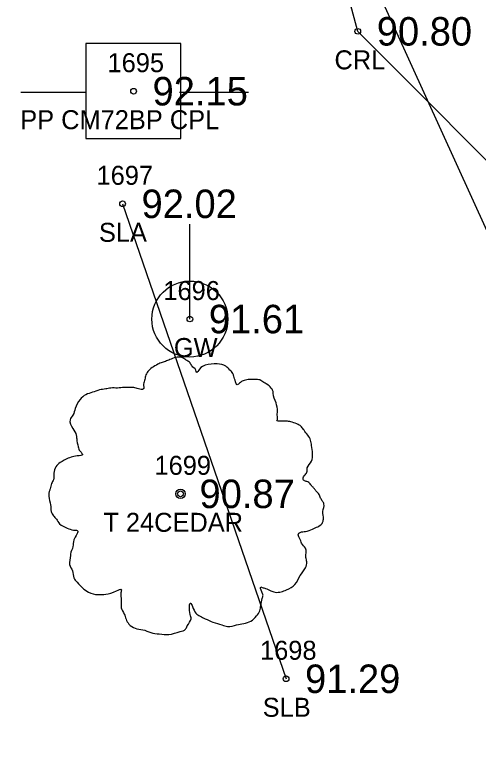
# Model space of a CAD drawing. Extents: x 2529517 to 2532038, y 935000 to 936944.
# Drawn here: x 2531034.45 to 2531058.87, y 935944.18 to 935982.7 of the extents above; entities that cross this region are included whole.
import ezdxf

# ---------------------------------------------------------------- set-up
doc = ezdxf.new("R2010")
doc.units = 0
for name, color, linetype in [('RD_EX_H2O', 7, 'Continuous'), ('RD_EX_H2O_txCode', 7, 'Continuous'), ('RD_EX_TX_H2O_ELEV', 7, 'Continuous'), ('RD_EX_TX_UT_ELEV', 7, 'Continuous'), ('RD_EX_TX_VEG_ELEV', 7, 'Continuous'), ('RD_EX_UT', 7, 'Continuous'), ('RD_EX_UT_txCode', 7, 'Continuous'), ('RD_EX_VEG', 7, 'Continuous'), ('RD_EX_VEG_txCode', 7, 'Continuous'), ('RD_HC_Survey_ELEV', 7, 'Continuous'), ('RD_SMD_Locator', 7, 'Continuous')]:
    doc.layers.add(name, color=color, linetype=linetype)

msp = doc.modelspace()

# ---------------------------------------------------------------- linework, layer by layer
at = {"layer": 'RD_EX_H2O'}
msp.add_lwpolyline([(2531078.875, 935952.281), (2531078.875, 935952.281), (2531082.899, 935955.367), (2531071.893, 935962.427), (2531052.521, 935981.817), (2531042.661, 936018.537), (2531050.401, 936038.586), (2531079.351, 936050.478), (2531076.459, 936052.289), (2531062.769, 936059.407), (2531060.273, 936060.115), (2531061.981, 936077.759), (2531053.988, 936081.477), (2531023.23, 936060.573), (2531009.04, 936063.638), (2530981.915, 936072.848), (2530952.276, 936069.689), (2530922.526, 936086.42), (2530896.36, 936118.007), (2530886.535, 936120.086), (2530870.436, 936126.503), (2530844.881, 936119.109), (2530827.398, 936131.929), (2530794.882, 936161.74)], dxfattribs=at)
at = {"layer": 'RD_EX_UT'}
for p, q in [((2531043.202, 935981.176), (2531038.202, 935981.176)), ((2531038.202, 935981.176), (2531038.202, 935976.176)), ((2531043.202, 935976.176), (2531043.202, 935981.176)), ((2531034.771, 935978.613), (2531038.241, 935978.613)), ((2531043.131, 935978.613), (2531046.771, 935978.613)), ((2531038.202, 935976.176), (2531043.202, 935976.176)), ((2531043.676, 935966.674), (2531043.676, 935971.674))]:
    msp.add_line(p, q, dxfattribs=at)
msp.add_circle((2531043.676, 935966.674), 1.999, dxfattribs=at)
at = {"layer": 'RD_EX_VEG'}
msp.add_line((2531040.132, 935972.739), (2531048.743, 935947.739), dxfattribs=at)
msp.add_lwpolyline([(2531065.966, 935956.737), (2531029.723, 936036.27), (2530913.111, 935955.889), (2530857.851, 935929.004), (2530845.595, 935970.773)], dxfattribs=at)
for centre, radius in [((2531043.184, 935957.474), 0.25), ((2531043.171, 935957.455), 0.0001)]:
    msp.add_circle(centre, radius, dxfattribs=at)
for points in [[(2531043.316, 935964.641), (2531043.016, 935964.666), (2531042.691, 935964.566), (2531042.441, 935964.466), (2531042.216, 935964.391), (2531041.991, 935964.291), (2531041.691, 935964.116), (2531041.467, 935963.916), (2531041.342, 935963.666), (2531041.292, 935963.442), (2531041.242, 935963.167), (2531041.242, 935962.992), (2531041.117, 935962.967), (2531040.967, 935962.992), (2531040.717, 935963.067), (2531040.467, 935963.067), (2531040.217, 935963.067), (2531039.867, 935963.042), (2531039.517, 935963.042), (2531039.243, 935962.992), (2531038.918, 935962.942), (2531038.543, 935962.817), (2531038.193, 935962.692), (2531037.893, 935962.442), (2531037.643, 935961.967), (2531037.518, 935961.617), (2531037.368, 935961.367), (2531037.518, 935960.918), (2531037.693, 935960.568), (2531037.718, 935960.368), (2531037.793, 935959.943), (2531037.893, 935959.718), (2531038.018, 935959.518), (2531037.943, 935959.493), (2531037.568, 935959.443), (2531037.268, 935959.343), (2531036.844, 935959.118), (2531036.619, 935958.894), (2531036.519, 935958.569), (2531036.494, 935958.219), (2531036.394, 935958.019), (2531036.319, 935957.744), (2531036.294, 935957.669), (2531036.244, 935957.344), (2531036.344, 935956.894), (2531036.369, 935956.545), (2531036.494, 935956.32), (2531036.644, 935956.145), (2531036.819, 935955.895), (2531037.218, 935955.67), (2531037.543, 935955.57), (2531037.743, 935955.545), (2531037.568, 935955.045), (2531037.518, 935954.695), (2531037.393, 935954.296), (2531037.393, 935954.221), (2531037.343, 935953.746), (2531037.493, 935953.421), (2531037.568, 935953.046), (2531037.743, 935952.821), (2531038.018, 935952.521), (2531038.343, 935952.296), (2531038.843, 935952.171), (2531039.243, 935952.196), (2531039.817, 935952.371), (2531040.067, 935952.446), (2531040.042, 935952.271), (2531040.067, 935951.897), (2531040.067, 935951.472), (2531040.217, 935951.147), (2531040.317, 935950.872), (2531040.467, 935950.622), (2531040.792, 935950.397), (2531041.192, 935950.322), (2531041.616, 935950.172), (2531042.066, 935950.097), (2531042.566, 935950.072), (2531043.166, 935950.222), (2531043.441, 935950.347), (2531043.541, 935950.522), (2531043.741, 935950.897), (2531043.691, 935951.122), (2531043.716, 935951.722), (2531043.815, 935951.547), (2531043.99, 935951.197), (2531044.49, 935950.897), (2531044.89, 935950.722), (2531045.365, 935950.572), (2531045.665, 935950.497), (2531046.139, 935950.572), (2531046.514, 935950.647), (2531046.889, 935950.772), (2531047.189, 935951.047), (2531047.364, 935951.322), (2531047.414, 935951.597), (2531047.489, 935951.972), (2531047.539, 935952.146)], [(2531047.539, 935952.146), (2531047.464, 935952.321), (2531047.414, 935952.571), (2531047.489, 935952.546), (2531047.664, 935952.496), (2531047.939, 935952.371), (2531048.164, 935952.296), (2531048.488, 935952.321), (2531048.763, 935952.421), (2531049.213, 935952.696), (2531049.488, 935953.171), (2531049.763, 935953.571), (2531049.838, 935953.896), (2531049.788, 935954.121), (2531049.763, 935954.62), (2531049.563, 935954.87), (2531049.513, 935954.995), (2531049.413, 935955.395), (2531049.488, 935955.445), (2531049.763, 935955.495), (2531050.138, 935955.62), (2531050.413, 935955.745), (2531050.638, 935955.92), (2531050.712, 935956.145), (2531050.688, 935956.545), (2531050.737, 935956.944), (2531050.663, 935957.094), (2531050.563, 935957.244), (2531050.488, 935957.444), (2531050.338, 935957.594), (2531050.238, 935957.744), (2531050.138, 935957.844), (2531050.013, 935957.994), (2531049.838, 935958.119), (2531049.688, 935958.169), (2531049.638, 935958.319), (2531049.788, 935958.519), (2531049.838, 935958.619), (2531049.863, 935958.844), (2531050.088, 935959.193), (2531050.138, 935959.593), (2531050.088, 935960.018), (2531050.038, 935960.293), (2531049.888, 935960.568), (2531049.688, 935960.818), (2531049.563, 935960.993), (2531049.388, 935961.118), (2531049.063, 935961.243), (2531048.813, 935961.292), (2531048.463, 935961.292), (2531048.264, 935961.342), (2531048.289, 935961.392), (2531048.289, 935961.542), (2531048.289, 935961.817), (2531048.214, 935962.267), (2531048.064, 935962.767), (2531048.064, 935962.792), (2531047.964, 935963.042), (2531047.739, 935963.242), (2531047.564, 935963.342), (2531047.364, 935963.467), (2531047.114, 935963.492), (2531046.814, 935963.492), (2531046.539, 935963.442), (2531046.339, 935963.342), (2531046.164, 935963.217), (2531046.089, 935963.367), (2531045.99, 935963.666), (2531045.94, 935963.816), (2531045.79, 935963.991), (2531045.565, 935964.191), (2531045.115, 935964.316), (2531044.49, 935964.241), (2531044.19, 935964.041), (2531044.04, 935963.866), (2531043.99, 935963.991), (2531043.79, 935964.191), (2531043.691, 935964.366), (2531043.516, 935964.491), (2531043.366, 935964.591), (2531043.266, 935964.641)]]:
    msp.add_spline(points, degree=3, dxfattribs=at)
at = {"layer": 'RD_SMD_Locator'}
for centre in [(2531052.521, 935981.817), (2531040.712, 935978.667), (2531040.132, 935972.739), (2531043.676, 935966.674), (2531043.184, 935957.474), (2531048.743, 935947.739)]:
    msp.add_circle(centre, 0.15, dxfattribs=at)

# ---------------------------------------------------------------- texts
at = {"layer": 'RD_EX_H2O_txCode'}
msp.add_text('CRL', height=1, dxfattribs=at).set_placement((2531051.293, 935979.817))
at = {"layer": 'RD_EX_TX_H2O_ELEV'}
msp.add_text('90.80', height=1.5, dxfattribs=at).set_placement((2531053.521, 935981.067))
at = {"layer": 'RD_EX_TX_UT_ELEV'}
msp.add_text('91.61', height=1.5, dxfattribs=at).set_placement((2531044.676, 935965.924))
at = {"layer": 'RD_EX_TX_VEG_ELEV'}
for s, p in [('92.02', (2531041.132, 935971.989)), ('90.87', (2531044.184, 935956.724)), ('91.29', (2531049.743, 935946.989))]:
    msp.add_text(s, height=1.5, dxfattribs=at).set_placement(p)
at = {"layer": 'RD_EX_UT_txCode'}
for s, p in [('1695', (2531039.341, 935979.667)), ('PP CM72BP CPL', (2531034.743, 935976.667)), ('1696', (2531042.282, 935967.674)), ('GW', (2531042.834, 935964.674))]:
    msp.add_text(s, height=1, dxfattribs=at).set_placement(p)
at = {"layer": 'RD_EX_VEG_txCode'}
for s, p in [('1697', (2531038.762, 935973.739)), ('SLA', (2531038.888, 935970.739)), ('1699', (2531041.814, 935958.474)), ('T 24CEDAR', (2531039.121, 935955.474)), ('1698', (2531047.373, 935948.739)), ('SLB', (2531047.515, 935945.739))]:
    msp.add_text(s, height=1, dxfattribs=at).set_placement(p)
at = {"layer": 'RD_HC_Survey_ELEV'}
msp.add_text('92.15', height=1.5, dxfattribs=at).set_placement((2531041.712, 935977.917))

doc.saveas('drawing.dxf')
